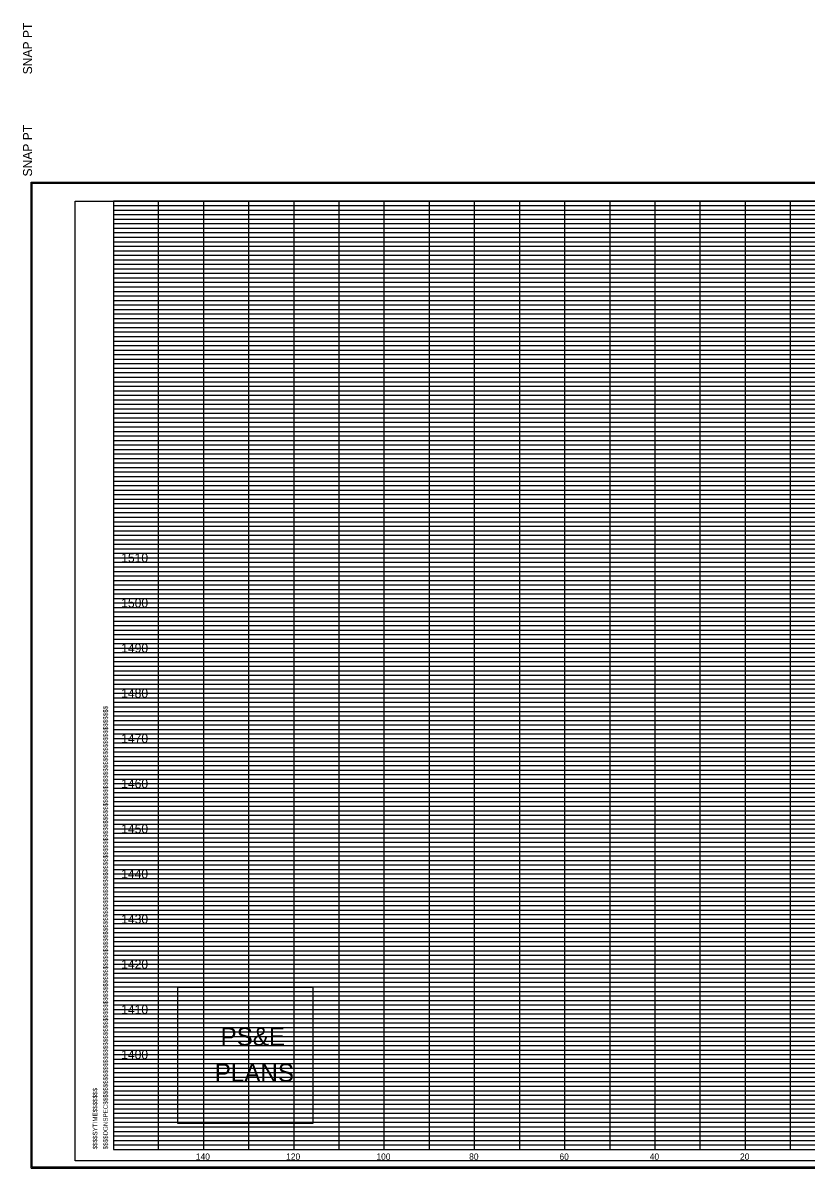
# Model space of a CAD drawing. Extents: x 980 to 2064, y 978 to 2267.
# Drawn here: x 1349.9 to 1523.4, y 1255.9 to 1509.4 of the extents above; entities that cross this region are included whole.
import ezdxf

# ---------------------------------------------------------------- set-up
doc = ezdxf.new("R2010")
doc.units = 0
for name, color, linetype in [('Default', 7, 'Continuous'), ('DESIGN - SHEET - Corner Text', 7, 'Continuous'), ('DESIGN - SHEET - Light Grid', 7, 'Continuous'), ('DESIGN - SHEET - Linework', 7, 'Continuous'), ('DESIGN - SHEET - Plot Shape', 7, 'Continuous')]:
    doc.layers.add(name, color=color, linetype=linetype)

# ---------------------------------------------------------------- blocks, each defined once
blk = doc.blocks.new('XSTSHT')
at = {"layer": 'DESIGN - SHEET - Corner Text'}
blk.add_text('SNAP PT  ', height=0.2, rotation=90, dxfattribs=at).set_placement((-1.803, -2.194))

msp = doc.modelspace()

# ---------------------------------------------------------------- linework, layer by layer
at = {"layer": 'DESIGN - SHEET - Corner Text'}
msp.add_lwpolyline([(1384.21, 1295.83), (1384.21, 1265.83), (1414.21, 1265.83), (1414.21, 1295.83)], close=True, dxfattribs=at)
at = {"layer": 'DESIGN - SHEET - Light Grid'}
for p, q in [((1370, 1469), (1450, 1469)), ((1450, 1469), (1530, 1469)), ((1370, 1468), (1450, 1468)), ((1370, 1467), (1450, 1467)), ((1370, 1466), (1450, 1466)), ((1450, 1468), (1530, 1468)), ((1450, 1467), (1530, 1467)), ((1450, 1466), (1530, 1466)), ((1370, 1465), (1450, 1465)), ((1370, 1464), (1450, 1464)), ((1450, 1465), (1530, 1465)), ((1450, 1464), (1530, 1464)), ((1370, 1463), (1450, 1463)), ((1370, 1462), (1450, 1462)), ((1370, 1461), (1450, 1461)), ((1450, 1463), (1530, 1463)), ((1450, 1462), (1530, 1462)), ((1450, 1461), (1530, 1461)), ((1370, 1459), (1450, 1459)), ((1450, 1459), (1530, 1459)), ((1370, 1458), (1450, 1458)), ((1370, 1457), (1450, 1457)), ((1370, 1456), (1450, 1456)), ((1450, 1458), (1530, 1458)), ((1450, 1457), (1530, 1457)), ((1450, 1456), (1530, 1456)), ((1370, 1455), (1450, 1455)), ((1370, 1454), (1450, 1454)), ((1450, 1455), (1530, 1455)), ((1450, 1454), (1530, 1454)), ((1370, 1453), (1450, 1453)), ((1370, 1452), (1450, 1452)), ((1370, 1451), (1450, 1451)), ((1450, 1453), (1530, 1453)), ((1450, 1452), (1530, 1452)), ((1450, 1451), (1530, 1451)), ((1370, 1449), (1450, 1449)), ((1370, 1448), (1450, 1448)), ((1450, 1449), (1530, 1449)), ((1450, 1448), (1530, 1448)), ((1370, 1447), (1450, 1447)), ((1370, 1446), (1450, 1446)), ((1450, 1447), (1530, 1447)), ((1450, 1446), (1530, 1446)), ((1370, 1445), (1450, 1445)), ((1370, 1444), (1450, 1444)), ((1370, 1443), (1450, 1443)), ((1450, 1445), (1530, 1445)), ((1450, 1444), (1530, 1444)), ((1450, 1443), (1530, 1443)), ((1370, 1442), (1450, 1442)), ((1370, 1441), (1450, 1441)), ((1450, 1442), (1530, 1442)), ((1450, 1441), (1530, 1441)), ((1370, 1439), (1450, 1439)), ((1370, 1438), (1450, 1438)), ((1450, 1439), (1530, 1439)), ((1450, 1438), (1530, 1438)), ((1370, 1437), (1450, 1437)), ((1370, 1436), (1450, 1436)), ((1450, 1437), (1530, 1437)), ((1450, 1436), (1530, 1436)), ((1370, 1435), (1450, 1435)), ((1370, 1434), (1450, 1434)), ((1370, 1433), (1450, 1433)), ((1450, 1435), (1530, 1435)), ((1450, 1434), (1530, 1434)), ((1450, 1433), (1530, 1433)), ((1370, 1432), (1450, 1432)), ((1370, 1431), (1450, 1431)), ((1450, 1432), (1530, 1432)), ((1450, 1431), (1530, 1431)), ((1370, 1429), (1450, 1429)), ((1370, 1428), (1450, 1428)), ((1450, 1429), (1530, 1429)), ((1450, 1428), (1530, 1428)), ((1370, 1427), (1450, 1427)), ((1370, 1426), (1450, 1426)), ((1450, 1427), (1530, 1427)), ((1450, 1426), (1530, 1426)), ((1370, 1425), (1450, 1425)), ((1370, 1424), (1450, 1424)), ((1370, 1423), (1450, 1423)), ((1450, 1425), (1530, 1425)), ((1450, 1424), (1530, 1424)), ((1450, 1423), (1530, 1423)), ((1370, 1422), (1450, 1422)), ((1370, 1421), (1450, 1421)), ((1450, 1422), (1530, 1422)), ((1450, 1421), (1530, 1421)), ((1370, 1419), (1450, 1419)), ((1370, 1418), (1450, 1418)), ((1450, 1419), (1530, 1419)), ((1450, 1418), (1530, 1418)), ((1370, 1417), (1450, 1417)), ((1370, 1416), (1450, 1416)), ((1370, 1415), (1450, 1415)), ((1450, 1417), (1530, 1417)), ((1450, 1416), (1530, 1416)), ((1450, 1415), (1530, 1415)), ((1370, 1414), (1450, 1414)), ((1370, 1413), (1450, 1413)), ((1450, 1414), (1530, 1414)), ((1450, 1413), (1530, 1413)), ((1370, 1412), (1450, 1412)), ((1370, 1411), (1450, 1411)), ((1450, 1412), (1530, 1412)), ((1450, 1411), (1530, 1411)), ((1370, 1409), (1450, 1409)), ((1370, 1408), (1450, 1408)), ((1450, 1409), (1530, 1409)), ((1450, 1408), (1530, 1408)), ((1370, 1407), (1450, 1407)), ((1370, 1406), (1450, 1406)), ((1370, 1405), (1450, 1405)), ((1450, 1407), (1530, 1407)), ((1450, 1406), (1530, 1406)), ((1450, 1405), (1530, 1405)), ((1370, 1404), (1450, 1404)), ((1370, 1403), (1450, 1403)), ((1450, 1404), (1530, 1404)), ((1450, 1403), (1530, 1403)), ((1370, 1402), (1450, 1402)), ((1370, 1401), (1450, 1401)), ((1450, 1402), (1530, 1402)), ((1450, 1401), (1530, 1401)), ((1370, 1399), (1450, 1399)), ((1370, 1398), (1450, 1398)), ((1450, 1399), (1530, 1399)), ((1450, 1398), (1530, 1398)), ((1370, 1397), (1450, 1397)), ((1370, 1396), (1450, 1396)), ((1370, 1395), (1450, 1395)), ((1450, 1397), (1530, 1397)), ((1450, 1396), (1530, 1396)), ((1450, 1395), (1530, 1395)), ((1370, 1394), (1450, 1394)), ((1370, 1393), (1450, 1393)), ((1450, 1394), (1530, 1394)), ((1450, 1393), (1530, 1393)), ((1370, 1392), (1450, 1392)), ((1370, 1391), (1450, 1391)), ((1450, 1392), (1530, 1392)), ((1450, 1391), (1530, 1391)), ((1370, 1389), (1450, 1389)), ((1370, 1388), (1450, 1388)), ((1450, 1389), (1530, 1389)), ((1450, 1388), (1530, 1388)), ((1370, 1387), (1450, 1387)), ((1370, 1386), (1450, 1386)), ((1370, 1385), (1450, 1385)), ((1450, 1387), (1530, 1387)), ((1450, 1386), (1530, 1386)), ((1450, 1385), (1530, 1385)), ((1370, 1384), (1450, 1384)), ((1370, 1383), (1450, 1383)), ((1450, 1384), (1530, 1384)), ((1450, 1383), (1530, 1383)), ((1370, 1382), (1450, 1382)), ((1370, 1381), (1450, 1381)), ((1450, 1382), (1530, 1382)), ((1450, 1381), (1530, 1381)), ((1370, 1379), (1450, 1379)), ((1370, 1378), (1450, 1378)), ((1370, 1377), (1450, 1377)), ((1450, 1379), (1530, 1379)), ((1450, 1378), (1530, 1378)), ((1450, 1377), (1530, 1377)), ((1370, 1376), (1450, 1376)), ((1370, 1375), (1450, 1375)), ((1450, 1376), (1530, 1376)), ((1450, 1375), (1530, 1375)), ((1370, 1374), (1450, 1374)), ((1370, 1373), (1450, 1373)), ((1370, 1372), (1450, 1372)), ((1450, 1374), (1530, 1374)), ((1450, 1373), (1530, 1373)), ((1450, 1372), (1530, 1372)), ((1370, 1371), (1450, 1371)), ((1450, 1371), (1530, 1371)), ((1370, 1369), (1450, 1369)), ((1370, 1368), (1450, 1368)), ((1370, 1367), (1450, 1367)), ((1450, 1369), (1530, 1369)), ((1450, 1368), (1530, 1368)), ((1450, 1367), (1530, 1367)), ((1370, 1366), (1450, 1366)), ((1370, 1365), (1450, 1365)), ((1450, 1366), (1530, 1366)), ((1450, 1365), (1530, 1365)), ((1370, 1364), (1450, 1364)), ((1370, 1363), (1450, 1363)), ((1370, 1362), (1450, 1362)), ((1450, 1364), (1530, 1364)), ((1450, 1363), (1530, 1363)), ((1450, 1362), (1530, 1362)), ((1370, 1361), (1450, 1361)), ((1450, 1361), (1530, 1361)), ((1370, 1359), (1450, 1359)), ((1370, 1358), (1450, 1358)), ((1370, 1357), (1450, 1357)), ((1450, 1359), (1530, 1359)), ((1450, 1358), (1530, 1358)), ((1450, 1357), (1530, 1357)), ((1370, 1356), (1450, 1356)), ((1370, 1355), (1450, 1355)), ((1450, 1356), (1530, 1356)), ((1450, 1355), (1530, 1355)), ((1370, 1354), (1450, 1354)), ((1370, 1353), (1450, 1353)), ((1370, 1352), (1450, 1352)), ((1450, 1354), (1530, 1354)), ((1450, 1353), (1530, 1353)), ((1450, 1352), (1530, 1352)), ((1370, 1351), (1450, 1351)), ((1450, 1351), (1530, 1351)), ((1370, 1349), (1450, 1349)), ((1370, 1348), (1450, 1348)), ((1370, 1347), (1450, 1347)), ((1450, 1349), (1530, 1349)), ((1450, 1348), (1530, 1348)), ((1450, 1347), (1530, 1347)), ((1370, 1346), (1450, 1346)), ((1370, 1345), (1450, 1345)), ((1370, 1344), (1450, 1344)), ((1450, 1346), (1530, 1346)), ((1450, 1345), (1530, 1345)), ((1450, 1344), (1530, 1344)), ((1370, 1343), (1450, 1343)), ((1370, 1342), (1450, 1342)), ((1450, 1343), (1530, 1343)), ((1450, 1342), (1530, 1342)), ((1370, 1341), (1450, 1341)), ((1370, 1339), (1450, 1339)), ((1450, 1341), (1530, 1341)), ((1450, 1339), (1530, 1339)), ((1370, 1338), (1450, 1338)), ((1370, 1337), (1450, 1337)), ((1450, 1338), (1530, 1338)), ((1450, 1337), (1530, 1337)), ((1370, 1336), (1450, 1336)), ((1370, 1335), (1450, 1335)), ((1370, 1334), (1450, 1334)), ((1450, 1336), (1530, 1336)), ((1450, 1335), (1530, 1335)), ((1450, 1334), (1530, 1334)), ((1370, 1333), (1450, 1333)), ((1370, 1332), (1450, 1332)), ((1450, 1333), (1530, 1333)), ((1450, 1332), (1530, 1332)), ((1370, 1331), (1450, 1331)), ((1370, 1329), (1450, 1329)), ((1450, 1331), (1530, 1331)), ((1450, 1329), (1530, 1329)), ((1370, 1328), (1450, 1328)), ((1370, 1327), (1450, 1327)), ((1450, 1328), (1530, 1328)), ((1450, 1327), (1530, 1327)), ((1370, 1326), (1450, 1326)), ((1370, 1325), (1450, 1325)), ((1370, 1324), (1450, 1324)), ((1450, 1326), (1530, 1326)), ((1450, 1325), (1530, 1325)), ((1450, 1324), (1530, 1324)), ((1370, 1323), (1450, 1323)), ((1370, 1322), (1450, 1322)), ((1450, 1323), (1530, 1323)), ((1450, 1322), (1530, 1322)), ((1370, 1321), (1450, 1321)), ((1370, 1319), (1450, 1319)), ((1450, 1321), (1530, 1321)), ((1450, 1319), (1530, 1319)), ((1370, 1318), (1450, 1318)), ((1370, 1317), (1450, 1317)), ((1450, 1318), (1530, 1318)), ((1450, 1317), (1530, 1317)), ((1370, 1316), (1450, 1316)), ((1370, 1315), (1450, 1315)), ((1370, 1314), (1450, 1314)), ((1450, 1316), (1530, 1316)), ((1450, 1315), (1530, 1315)), ((1450, 1314), (1530, 1314)), ((1370, 1313), (1450, 1313)), ((1370, 1312), (1450, 1312)), ((1450, 1313), (1530, 1313)), ((1450, 1312), (1530, 1312)), ((1370, 1311), (1450, 1311)), ((1370, 1309), (1450, 1309)), ((1450, 1311), (1530, 1311)), ((1450, 1309), (1530, 1309)), ((1370, 1308), (1450, 1308)), ((1370, 1307), (1450, 1307)), ((1370, 1306), (1450, 1306)), ((1450, 1308), (1530, 1308)), ((1450, 1307), (1530, 1307)), ((1450, 1306), (1530, 1306)), ((1370, 1305), (1450, 1305)), ((1370, 1304), (1450, 1304)), ((1450, 1305), (1530, 1305)), ((1450, 1304), (1530, 1304)), ((1370, 1303), (1450, 1303)), ((1370, 1302), (1450, 1302)), ((1370, 1301), (1450, 1301)), ((1450, 1303), (1530, 1303)), ((1450, 1302), (1530, 1302)), ((1450, 1301), (1530, 1301)), ((1370, 1299), (1450, 1299)), ((1450, 1299), (1530, 1299)), ((1370, 1298), (1450, 1298)), ((1370, 1297), (1450, 1297)), ((1370, 1296), (1450, 1296)), ((1450, 1298), (1530, 1298)), ((1450, 1297), (1530, 1297)), ((1450, 1296), (1530, 1296)), ((1370, 1295), (1450, 1295)), ((1370, 1294), (1450, 1294)), ((1450, 1295), (1530, 1295)), ((1450, 1294), (1530, 1294)), ((1370, 1293), (1450, 1293)), ((1370, 1292), (1450, 1292)), ((1370, 1291), (1450, 1291)), ((1450, 1293), (1530, 1293)), ((1450, 1292), (1530, 1292)), ((1450, 1291), (1530, 1291)), ((1370, 1289), (1450, 1289)), ((1450, 1289), (1530, 1289)), ((1370, 1288), (1450, 1288)), ((1370, 1287), (1450, 1287)), ((1370, 1286), (1450, 1286)), ((1450, 1288), (1530, 1288)), ((1450, 1287), (1530, 1287)), ((1450, 1286), (1530, 1286)), ((1370, 1285), (1450, 1285)), ((1370, 1284), (1450, 1284)), ((1450, 1285), (1530, 1285)), ((1450, 1284), (1530, 1284)), ((1370, 1283), (1450, 1283)), ((1370, 1282), (1450, 1282)), ((1370, 1281), (1450, 1281)), ((1450, 1283), (1530, 1283)), ((1450, 1282), (1530, 1282)), ((1450, 1281), (1530, 1281)), ((1370, 1279), (1450, 1279)), ((1450, 1279), (1530, 1279)), ((1370, 1278), (1450, 1278)), ((1370, 1277), (1450, 1277)), ((1370, 1276), (1450, 1276)), ((1450, 1278), (1530, 1278)), ((1450, 1277), (1530, 1277)), ((1450, 1276), (1530, 1276)), ((1370, 1275), (1450, 1275)), ((1370, 1274), (1450, 1274)), ((1370, 1273), (1450, 1273)), ((1450, 1275), (1530, 1275)), ((1450, 1274), (1530, 1274)), ((1450, 1273), (1530, 1273)), ((1370, 1272), (1450, 1272)), ((1370, 1271), (1450, 1271)), ((1450, 1272), (1530, 1272)), ((1450, 1271), (1530, 1271)), ((1370, 1269), (1450, 1269)), ((1370, 1268), (1450, 1268)), ((1450, 1269), (1530, 1269)), ((1450, 1268), (1530, 1268)), ((1370, 1267), (1450, 1267)), ((1370, 1266), (1450, 1266)), ((1450, 1267), (1530, 1267)), ((1450, 1266), (1530, 1266)), ((1370, 1265), (1450, 1265)), ((1370, 1264), (1450, 1264)), ((1370, 1263), (1450, 1263)), ((1450, 1265), (1530, 1265)), ((1450, 1264), (1530, 1264)), ((1450, 1263), (1530, 1263)), ((1370, 1262), (1450, 1262)), ((1370, 1261), (1450, 1261)), ((1450, 1262), (1530, 1262)), ((1450, 1261), (1530, 1261))]:
    msp.add_line(p, q, dxfattribs=at)
at = {"layer": 'DESIGN - SHEET - Linework'}
for p, q in [((1351.77, 1255.86), (1351.77, 1474.14)), ((1351.77, 1474.14), (1692.17, 1474.14)), ((1380, 1260), (1380, 1470)), ((1390, 1260), (1390, 1470)), ((1400, 1260), (1400, 1470)), ((1410, 1260), (1410, 1470)), ((1420, 1260), (1420, 1470)), ((1430, 1260), (1430, 1470)), ((1440, 1260), (1440, 1470)), ((1450, 1260), (1450, 1470)), ((1460, 1260), (1460, 1470)), ((1470, 1260), (1470, 1470)), ((1480, 1260), (1480, 1470)), ((1490, 1260), (1490, 1470)), ((1500, 1260), (1500, 1470)), ((1510, 1260), (1510, 1470)), ((1520, 1260), (1520, 1470)), ((1370, 1460), (1650, 1460)), ((1370, 1450), (1690, 1450)), ((1370, 1440), (1690, 1440)), ((1370, 1430), (1690, 1430)), ((1370, 1420), (1690, 1420)), ((1370, 1410), (1690, 1410)), ((1370, 1400), (1690, 1400)), ((1370, 1390), (1690, 1390)), ((1370, 1380), (1690, 1380)), ((1370, 1370), (1690, 1370)), ((1370, 1360), (1690, 1360)), ((1370, 1350), (1690, 1350)), ((1370, 1340), (1690, 1340)), ((1370, 1330), (1690, 1330)), ((1370, 1320), (1690, 1320)), ((1370, 1310), (1690, 1310)), ((1370, 1300), (1690, 1300)), ((1370, 1290), (1690, 1290)), ((1370, 1280), (1690, 1280)), ((1370, 1270), (1690, 1270)), ((1351.77, 1255.86), (1692.17, 1255.86))]:
    msp.add_line(p, q, dxfattribs=at)
msp.add_lwpolyline([(1370, 1470), (1370, 1260), (1690, 1260), (1690, 1470), (1370, 1470)], dxfattribs=at)
at = {"layer": 'DESIGN - SHEET - Plot Shape'}
for points in [[(1351.97, 1473.94), (1691.97, 1473.94), (1691.97, 1256.06), (1351.97, 1256.06)], [(1361.5, 1470), (1690, 1470), (1690, 1257.5), (1361.5, 1257.5)]]:
    msp.add_lwpolyline(points, close=True, dxfattribs=at)

# ---------------------------------------------------------------- block references
at = {"layer": 'Default', "xscale": 10, "yscale": 10}
msp.add_blockref('XSTSHT', (1370, 1520), dxfattribs=at)

# ---------------------------------------------------------------- texts
at = {"layer": 'Default'}
for s, height, p in [('     1510     ', 2, (1368.01, 1390)), ('     1500     ', 2, (1368.01, 1380)), ('     1490     ', 2, (1368.01, 1370)), ('     1480     ', 2, (1368.01, 1360)), ('     1470     ', 2, (1368.01, 1350)), ('     1460     ', 2, (1368.01, 1340)), ('     1450     ', 2, (1368.01, 1330)), ('     1440     ', 2, (1368.01, 1320)), ('     1430     ', 2, (1368.01, 1310)), ('     1420     ', 2, (1368.01, 1300)), ('     1410     ', 2, (1368.01, 1290)), ('     1400     ', 2, (1368.01, 1280)), ('     140     ', 1.4, (1385.65, 1257.7)), ('     120     ', 1.4, (1405.65, 1257.7)), ('     100     ', 1.4, (1425.65, 1257.7)), ('     80     ', 1.4, (1446.2, 1257.7)), ('     60     ', 1.4, (1466.2, 1257.7)), ('     40     ', 1.4, (1486.2, 1257.7)), ('     20     ', 1.4, (1506.2, 1257.7))]:
    msp.add_text(s, height=height, dxfattribs=at).set_placement(p)
at = {"layer": 'DESIGN - SHEET - Corner Text'}
for s, height, p in [('  SNAP PT', 2, (1351.97, 1473.94)), ('$$$$DGNSPEC$$$$$$$$$$$$$$$$$$$$$$$$$$$$$$$$$$$$$$$$$$$$$$$$$$$$$$$$$$$$$$$$$$$$$$$$$$$$$$$$$$$$$$$$$$$$$$$$$$$$$$$$$$$$$$$$$$$', 1.00002, (1368.74, 1260)), ('$$$$SYTIME$$$$$$$', 1, (1366.42, 1260))]:
    msp.add_text(s, height=height, rotation=90, dxfattribs=at).set_placement(p)
for s, p in [('PS&E', (1393.73, 1283)), ('PLANS', (1392.44, 1275))]:
    msp.add_text(s, height=4, dxfattribs=at).set_placement(p)

doc.saveas('drawing.dxf')
